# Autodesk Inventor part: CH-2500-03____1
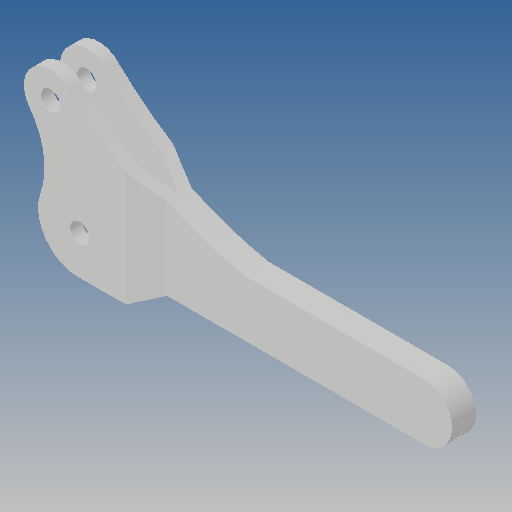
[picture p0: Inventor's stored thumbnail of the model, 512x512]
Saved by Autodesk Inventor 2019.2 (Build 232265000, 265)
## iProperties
Created: 2012-09
Part Number: CH-2500-03____1
Material: Ogólny
Document SubType Name: Modeling
Designer: CADENGINEERING4
Density: 1 g/cm^3
Appearance: Domyślna
Author: CADENGINEERING4
Revision Number: ÈÎºÎ
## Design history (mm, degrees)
feature "NONE" [ÊäÈë]
feature "ÊäÈë2"
node "Bryła1"
node "Bryła2"
